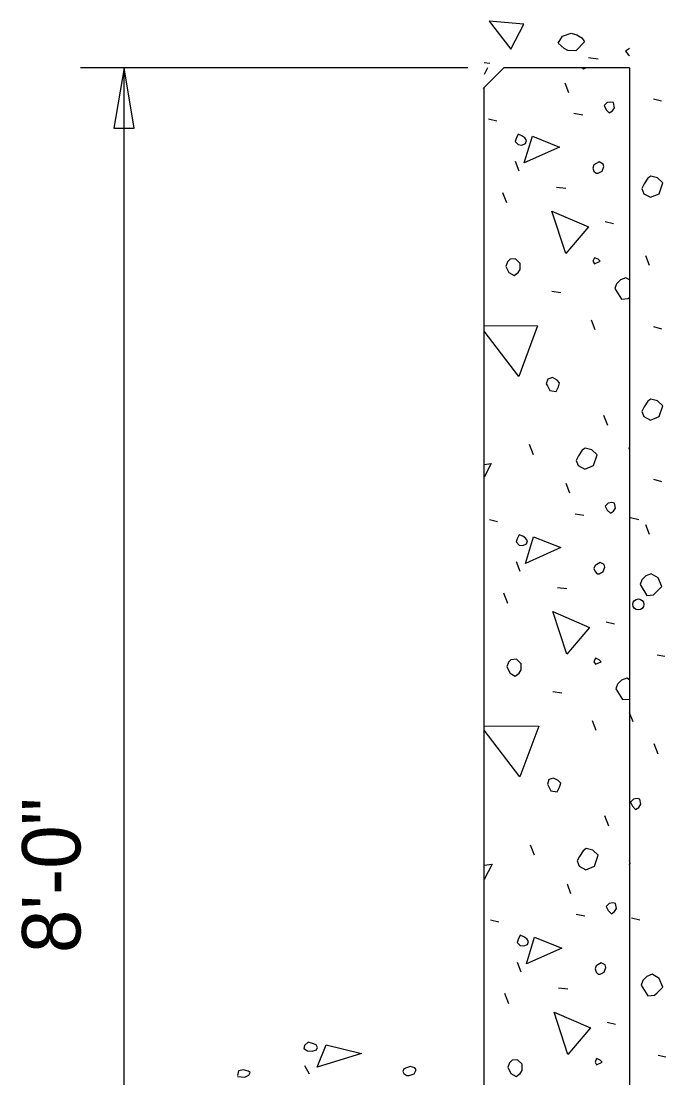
# Model space of a CAD drawing. Extents: x 112310.1 to 112345.4, y 111943.5 to 111959.3.
# Drawn here: x 112319.092 to 112320.205, y 111950.107 to 111951.931 of the extents above; entities that cross this region are included whole.
import ezdxf

# ---------------------------------------------------------------- set-up
doc = ezdxf.new("R2010")
doc.units = 0
for name, color, linetype in [('Dimension', 7, 'Continuous'), ('Miscellaneous', 7, 'Continuous'), ('PileConc', 7, 'Continuous'), ('TextStructures', 7, 'Continuous')]:
    doc.layers.add(name, color=color, linetype=linetype)

msp = doc.modelspace()

# ---------------------------------------------------------------- linework, layer by layer
at = {"layer": 'Dimension'}
msp.add_line((112319.8636, 111951.8505), (112319.1951, 111951.8505), dxfattribs=at)
msp.add_lwpolyline([(112319.2701, 111948.6596), (112319.2701, 111948.9374), (112319.3217, 111948.9374), (112319.2701, 111948.9599), (112319.2184, 111948.9824), (112319.2701, 111948.9824), (112319.2701, 111951.8505)], dxfattribs=at)
msp.add_lwpolyline([(112319.2701, 111951.8505), (112319.2524, 111951.7464), (112319.2877, 111951.7464)], close=True, dxfattribs=at)
at = {"layer": 'Miscellaneous'}
for p, q in [((112319.8914, 111951.8598), (112319.9011, 111951.8586)), ((112320.0717, 111951.8682), (112320.0885, 111951.8661)), ((112320.0377, 111951.8075), (112320.0315, 111951.8243)), ((112320.1836, 111951.7971), (112320.1978, 111951.7936)), ((112320.0465, 111951.7721), (112320.0616, 111951.7695)), ((112319.8989, 111951.7624), (112319.9131, 111951.7589)), ((112319.952, 111951.6722), (112319.9458, 111951.689)), ((112320.0165, 111951.6448), (112320.0324, 111951.6431)), ((112319.9308, 111951.6174), (112319.9237, 111951.6351)), ((112320.1005, 111951.5856), (112320.1146, 111951.5821)), ((112320.1767, 111951.5092), (112320.1705, 111951.526)), ((112320.0085, 111951.4654), (112320.0236, 111951.4628)), ((112320.0828, 111951.3982), (112320.0766, 111951.415)), ((112320.1836, 111951.4039), (112320.1978, 111951.4004)), ((112320.1049, 111951.233), (112320.0978, 111951.2506)), ((112319.9767, 111951.1826), (112319.9696, 111951.2003)), ((112320.1422, 111951.1922), (112320.1411, 111951.195)), ((112320.0395, 111951.1163), (112320.0333, 111951.1331)), ((112320.1836, 111951.1404), (112320.1978, 111951.1369)), ((112319.9007, 111951.0712), (112319.9148, 111951.0677)), ((112320.0483, 111951.0809), (112320.0633, 111951.0783)), ((112320.1441, 111951.0745), (112320.1583, 111951.071)), ((112320.1767, 111951.0449), (112320.1705, 111951.0617)), ((112319.9537, 111950.9811), (112319.9476, 111950.9978)), ((112319.9325, 111950.9263), (112319.9255, 111950.9439)), ((112320.0183, 111950.9537), (112320.0342, 111950.9519)), ((112320.1022, 111950.8944), (112320.1164, 111950.8909)), ((112320.1901, 111950.8376), (112320.2033, 111950.835)), ((112320.0103, 111950.7742), (112320.0253, 111950.7716)), ((112320.0846, 111950.707), (112320.0784, 111950.7238)), ((112320.1485, 111950.7218), (112320.1423, 111950.7375)), ((112320.1918, 111950.6661), (112320.1848, 111950.6838)), ((112320.1067, 111950.5418), (112320.0996, 111950.5594)), ((112319.9785, 111950.4914), (112319.9714, 111950.5091)), ((112320.0412, 111950.4251), (112320.0351, 111950.4419)), ((112319.9025, 111950.38), (112319.9166, 111950.3765)), ((112320.0501, 111950.3897), (112320.0651, 111950.3871)), ((112320.1459, 111950.3833), (112320.16, 111950.3798)), ((112319.9555, 111950.2899), (112319.9493, 111950.3066)), ((112319.9343, 111950.2351), (112319.9272, 111950.2527)), ((112320.02, 111950.2625), (112320.0359, 111950.2607)), ((112320.104, 111950.2032), (112320.1181, 111950.1997)), ((112320.1918, 111950.1464), (112320.2051, 111950.1438)), ((112319.5903, 111950.1137), (112319.5819, 111950.1281))]:
    msp.add_line(p, q, dxfattribs=at)
for points in [[(112319.9378, 111951.8831), (112319.9599, 111951.926), (112319.9001, 111951.9312), (112319.9378, 111951.8831)], [(112320.0647, 111951.8952), (112320.0497, 111951.8801), (112320.036, 111951.8804), (112320.0298, 111951.8838), (112320.0192, 111951.893), (112320.0266, 111951.9051), (112320.0416, 111951.9106), (112320.0515, 111951.9077), (112320.0599, 111951.9021), (112320.0647, 111951.8952)], [(112320.1422, 111951.884), (112320.1356, 111951.8796), (112320.1399, 111951.8736)], [(112320.1399, 111951.8736), (112320.1422, 111951.8721)], [(112319.8974, 111951.8505), (112319.8914, 111951.839)], [(112320.0605, 111951.8505), (112320.0633, 111951.849), (112320.067, 111951.8505)], [(112320.1022, 111951.7783), (112320.1075, 111951.773), (112320.1128, 111951.7765), (112320.1164, 111951.7818), (112320.1146, 111951.7907), (112320.1102, 111951.7916), (112320.104, 111951.7907), (112320.0987, 111951.7854), (112320.1022, 111951.7783)], [(112319.9502, 111951.7182), (112319.9564, 111951.7173), (112319.9626, 111951.72), (112319.9643, 111951.7253), (112319.9617, 111951.7297), (112319.9564, 111951.7332), (112319.9502, 111951.7359), (112319.9467, 111951.7288), (112319.9449, 111951.7235), (112319.9502, 111951.7182)], [(112319.9608, 111951.6864), (112319.975, 111951.7324), (112320.0218, 111951.7138), (112319.9608, 111951.6864)], [(112320.0846, 111951.6687), (112320.0881, 111951.6687), (112320.0952, 111951.6722), (112320.0978, 111951.6802), (112320.0969, 111951.6846), (112320.0899, 111951.6882), (112320.081, 111951.6829), (112320.0793, 111951.6776), (112320.081, 111951.6722), (112320.0846, 111951.6687)], [(112320.167, 111951.6334), (112320.1785, 111951.6272), (112320.1935, 111951.6334), (112320.1997, 111951.652), (112320.1909, 111951.6608), (112320.1794, 111951.6635), (112320.1741, 111951.66), (112320.1679, 111951.6502), (112320.1635, 111951.6423), (112320.167, 111951.6334)], [(112320.0324, 111951.5299), (112320.0085, 111951.6033), (112320.0713, 111951.5759), (112320.0324, 111951.5299)], [(112319.929, 111951.5078), (112319.9343, 111951.4972), (112319.9431, 111951.4919), (112319.9502, 111951.4972), (112319.9537, 111951.5025), (112319.9537, 111951.5131), (112319.9458, 111951.5211), (112319.9361, 111951.5202), (112319.9316, 111951.5158), (112319.929, 111951.5078)], [(112320.0819, 111951.5123), (112320.0916, 111951.5167), (112320.0881, 111951.5202), (112320.0819, 111951.5229), (112320.0793, 111951.5167), (112320.0819, 111951.5123)], [(112320.1422, 111951.4847), (112320.1358, 111951.4884), (112320.127, 111951.4849), (112320.1199, 111951.4778), (112320.1173, 111951.4698)], [(112320.1173, 111951.4698), (112320.1287, 111951.4513), (112320.1402, 111951.4522), (112320.1422, 111951.4542)], [(112319.8914, 111951.4061), (112319.9838, 111951.4053), (112319.9511, 111951.3178)], [(112319.9511, 111951.3178), (112319.8914, 111951.3963)], [(112320.0006, 111951.3019), (112320.005, 111951.2939), (112320.0156, 111951.2922), (112320.02, 111951.3001), (112320.0218, 111951.3072), (112320.0174, 111951.3116), (112320.0094, 111951.316), (112320.0015, 111951.3134), (112319.9988, 111951.3054), (112320.0006, 111951.3019)], [(112320.167, 111951.2487), (112320.1785, 111951.2425), (112320.1935, 111951.2487), (112320.1997, 111951.2672), (112320.1909, 111951.2761), (112320.1794, 111951.2787), (112320.1741, 111951.2752), (112320.1679, 111951.2654), (112320.1635, 111951.2575), (112320.167, 111951.2487)], [(112320.0536, 111951.164), (112320.0651, 111951.1578), (112320.0801, 111951.164), (112320.0863, 111951.1826), (112320.0775, 111951.1914), (112320.066, 111951.1941), (112320.0607, 111951.1905), (112320.0545, 111951.1808), (112320.0501, 111951.1729), (112320.0536, 111951.164)], [(112319.8914, 111951.166), (112319.9034, 111951.1676), (112319.8914, 111951.1443)], [(112320.104, 111951.0871), (112320.1093, 111951.0818), (112320.1146, 111951.0853), (112320.1181, 111951.0907), (112320.1164, 111951.0995), (112320.112, 111951.1004), (112320.1058, 111951.0995), (112320.1005, 111951.0942), (112320.104, 111951.0871)], [(112319.952, 111951.027), (112319.9582, 111951.0261), (112319.9643, 111951.0288), (112319.9661, 111951.0341), (112319.9635, 111951.0385), (112319.9582, 111951.042), (112319.952, 111951.0447), (112319.9484, 111951.0376), (112319.9467, 111951.0323), (112319.952, 111951.027)], [(112319.9626, 111950.9952), (112319.9767, 111951.0412), (112320.0236, 111951.0226), (112319.9626, 111950.9952)], [(112320.0863, 111950.9775), (112320.0899, 111950.9775), (112320.0969, 111950.9811), (112320.0996, 111950.989), (112320.0987, 111950.9934), (112320.0916, 111950.997), (112320.0828, 111950.9917), (112320.081, 111950.9864), (112320.0828, 111950.9811), (112320.0863, 111950.9775)], [(112320.1609, 111950.9587), (112320.1724, 111950.9401), (112320.1839, 111950.941), (112320.1883, 111950.9454), (112320.198, 111950.9552), (112320.1918, 111950.9702), (112320.1795, 111950.9773), (112320.1706, 111950.9737), (112320.1636, 111950.9667), (112320.1609, 111950.9587)], [(112320.0342, 111950.8387), (112320.0103, 111950.9121), (112320.0731, 111950.8847), (112320.0342, 111950.8387)], [(112319.9308, 111950.8166), (112319.9361, 111950.806), (112319.9449, 111950.8007), (112319.952, 111950.806), (112319.9555, 111950.8113), (112319.9555, 111950.822), (112319.9476, 111950.8299), (112319.9378, 111950.829), (112319.9334, 111950.8246), (112319.9308, 111950.8166)], [(112320.0837, 111950.8211), (112320.0934, 111950.8255), (112320.0899, 111950.829), (112320.0837, 111950.8317), (112320.081, 111950.8255), (112320.0837, 111950.8211)], [(112320.1422, 111950.7945), (112320.1376, 111950.7972), (112320.1287, 111950.7937), (112320.1217, 111950.7866), (112320.119, 111950.7786)], [(112320.119, 111950.7786), (112320.1305, 111950.7601), (112320.142, 111950.761), (112320.1422, 111950.7612)], [(112319.8914, 111950.715), (112319.9856, 111950.7141), (112319.9529, 111950.6266)], [(112319.9529, 111950.6266), (112319.8914, 111950.7075)], [(112320.0024, 111950.6107), (112320.0068, 111950.6027), (112320.0174, 111950.601), (112320.0218, 111950.6089), (112320.0236, 111950.616), (112320.0191, 111950.6204), (112320.0112, 111950.6248), (112320.0032, 111950.6222), (112320.0006, 111950.6142), (112320.0024, 111950.6107)], [(112320.1476, 111950.576), (112320.1529, 111950.5707), (112320.1583, 111950.5742), (112320.1618, 111950.5795), (112320.16, 111950.5883), (112320.1556, 111950.5892), (112320.1494, 111950.5883), (112320.1441, 111950.583), (112320.1476, 111950.576)], [(112320.0554, 111950.4728), (112320.0669, 111950.4666), (112320.0819, 111950.4728), (112320.0881, 111950.4914), (112320.0793, 111950.5002), (112320.0678, 111950.5029), (112320.0625, 111950.4993), (112320.0563, 111950.4896), (112320.0519, 111950.4817), (112320.0554, 111950.4728)], [(112319.8914, 111950.4745), (112319.9051, 111950.4764), (112319.8914, 111950.4497)], [(112320.1423, 111950.475), (112320.1432, 111950.4779), (112320.1423, 111950.4823), (112320.1423, 111950.4823)], [(112320.1058, 111950.3959), (112320.1111, 111950.3906), (112320.1164, 111950.3942), (112320.1199, 111950.3995), (112320.1181, 111950.4083), (112320.1137, 111950.4092), (112320.1075, 111950.4083), (112320.1022, 111950.403), (112320.1058, 111950.3959)], [(112319.9537, 111950.3358), (112319.9599, 111950.3349), (112319.9661, 111950.3376), (112319.9679, 111950.3429), (112319.9652, 111950.3473), (112319.9599, 111950.3508), (112319.9537, 111950.3535), (112319.9502, 111950.3464), (112319.9484, 111950.3411), (112319.9537, 111950.3358)], [(112319.9643, 111950.304), (112319.9785, 111950.35), (112320.0253, 111950.3314), (112319.9643, 111950.304)], [(112320.0881, 111950.2863), (112320.0916, 111950.2863), (112320.0987, 111950.2899), (112320.1013, 111950.2978), (112320.1005, 111950.3022), (112320.0934, 111950.3058), (112320.0846, 111950.3005), (112320.0828, 111950.2952), (112320.0846, 111950.2899), (112320.0881, 111950.2863)], [(112320.1627, 111950.2675), (112320.1742, 111950.2489), (112320.1857, 111950.2498), (112320.1901, 111950.2542), (112320.1998, 111950.264), (112320.1936, 111950.279), (112320.1812, 111950.2861), (112320.1724, 111950.2825), (112320.1653, 111950.2755), (112320.1627, 111950.2675)], [(112320.0359, 111950.1475), (112320.0121, 111950.2209), (112320.0748, 111950.1935), (112320.0359, 111950.1475)], [(112319.5866, 111950.1541), (112319.5945, 111950.1535), (112319.6021, 111950.1556), (112319.6039, 111950.1598), (112319.6016, 111950.1641), (112319.5955, 111950.1668), (112319.5877, 111950.169), (112319.5817, 111950.1634), (112319.5805, 111950.1581), (112319.5866, 111950.1541)], [(112319.6032, 111950.126), (112319.6189, 111950.1644), (112319.6798, 111950.1496), (112319.6032, 111950.126)], [(112320.0854, 111950.1299), (112320.0952, 111950.1343), (112320.0916, 111950.1378), (112320.0854, 111950.1405), (112320.0828, 111950.1343), (112320.0854, 111950.1299)], [(112319.7578, 111950.1116), (112319.7618, 111950.1113), (112319.7705, 111950.1143), (112319.7743, 111950.1213), (112319.7717, 111950.1246), (112319.7639, 111950.1269), (112319.7529, 111950.123), (112319.7511, 111950.1184), (112319.7527, 111950.115), (112319.7578, 111950.1116)], [(112319.9325, 111950.1255), (112319.9378, 111950.1148), (112319.9467, 111950.1095), (112319.9537, 111950.1148), (112319.9573, 111950.1201), (112319.9573, 111950.1308), (112319.9493, 111950.1387), (112319.9396, 111950.1378), (112319.9352, 111950.1334), (112319.9325, 111950.1255)], [(112319.4659, 111950.1097), (112319.4783, 111950.1086), (112319.4856, 111950.1119), (112319.4879, 111950.1164), (112319.484, 111950.119), (112319.4762, 111950.1211), (112319.4673, 111950.1196), (112319.4668, 111950.1163), (112319.4659, 111950.1112)]]:
    msp.add_lwpolyline(points, dxfattribs=at)
msp.add_circle((112320.1576, 111950.9244), 0.00957, dxfattribs=at)
at = {"layer": 'PileConc'}
for p, q in [((112319.8897, 111951.815), (112319.9252, 111951.8505)), ((112320.1423, 111951.8505), (112319.9253, 111951.8505)), ((112320.1422, 111951.8505), (112320.1422, 111949.007)), ((112319.8914, 111949.007), (112319.8914, 111951.8167))]:
    msp.add_line(p, q, dxfattribs=at)

# ---------------------------------------------------------------- texts
at = {"layer": 'TextStructures'}
msp.add_text('8\'-0"', height=0.1008, rotation=90, dxfattribs=at).set_placement((112319.1947, 111950.3226))

doc.saveas('drawing.dxf')
